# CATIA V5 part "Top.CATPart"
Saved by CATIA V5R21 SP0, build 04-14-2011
Part number: Part1.8
Material "Fire Red": density 7860 kg/m3, Young's modulus 2e+11 Pa, Poisson ratio 0.266
Bounding box of the stored display mesh (mm): x 0 to 60, y -19 to 19, z -18.99 to 18.99
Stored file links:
  G:\CATIA\Class\Project_1\Top.CATPart
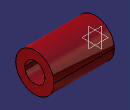
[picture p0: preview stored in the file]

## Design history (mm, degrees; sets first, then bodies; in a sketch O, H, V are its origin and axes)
Body1 (main body), material "Fire Red"
  Sketch1 on yz-plane, origin (0, 0, 0), H (0, 1, 0), V (0, 0, 1)
    circle A1 centre (0, 0) radius 19
    circle A2 centre (0, 0) radius 10
    radius A2 = 10
    radius A1 = 19
  Pad1: profile Sketch1, direction (1, 0, 0), length 60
